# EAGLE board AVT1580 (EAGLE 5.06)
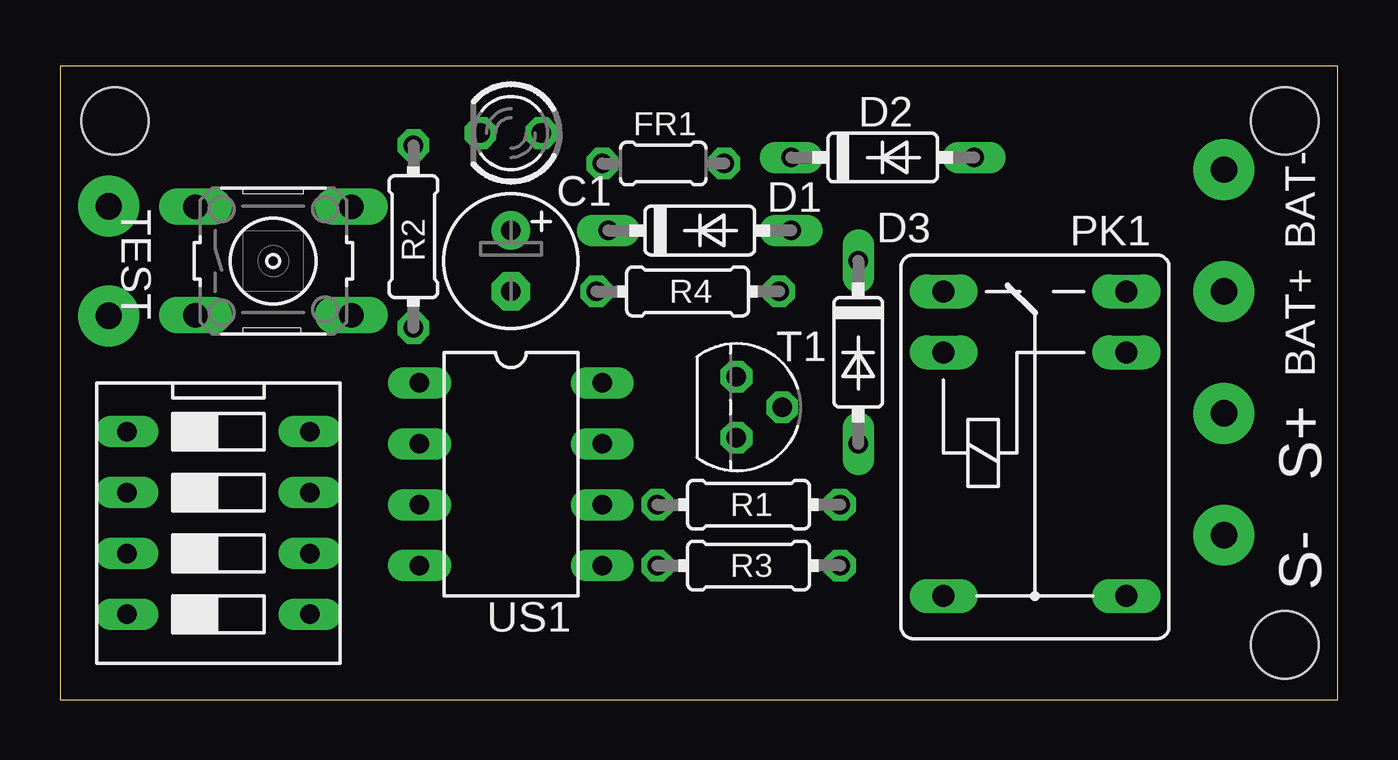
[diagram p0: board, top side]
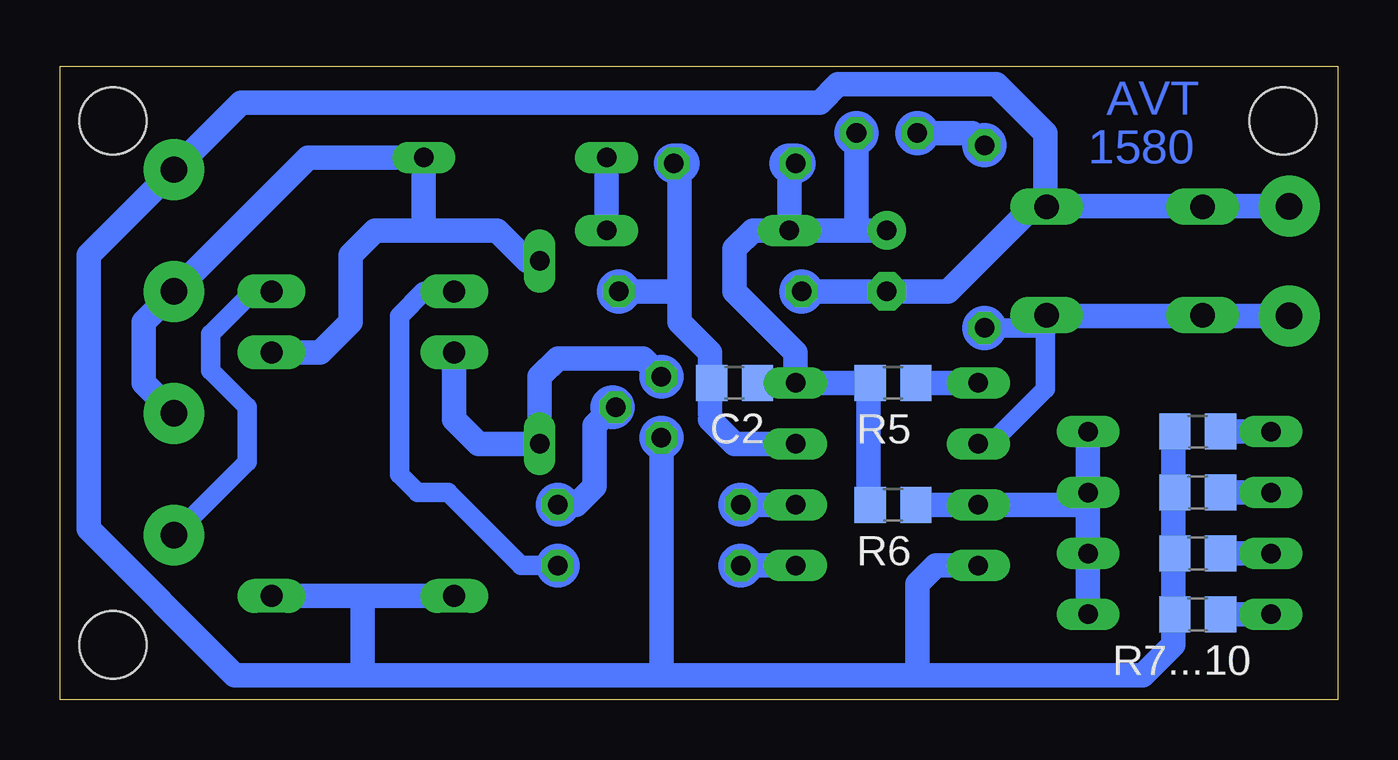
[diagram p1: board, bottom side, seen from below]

Size 53.26 x 26.41 mm. Coordinates in mm from the lower left corner, seen from the top.
Outline: 0,0 53.26,0 53.26,26.41 0,26.41 0,0
Copper layers (1*16): Top 0.035mm / dielectric 1.5mm / Bottom 0.035mm
Design rules "default": minimum track width 10mil, minimum drill 24mil, track to track 8mil, track to pad 8mil, pad to pad 8mil, via to via 8mil, smd to smd 8mil, copper to edge 40mil, drill to drill 8mil, minimum pad ring 10mil, minimum via ring 8mil, stop-mask expansion 4mil, vias tented up to drill 0mil, thermal gap 10mil
Holes 2.8 mm at 2.29,24.13 51.05,2.29 51.05,24.13

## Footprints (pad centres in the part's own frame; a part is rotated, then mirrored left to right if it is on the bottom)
E2,5-6 = drill 0.813 pad 1.6 round: + -1.27,0 | drill 0.813 pad 1.6 octagon: - 1.27,0
C0805 = smd 1.3 x 1.5: 1 -0.95,0; 2 0.95,0
DO35-7 = drill 0.813 long: A 3.81,0; C -3.81,0
LED3MM = drill 0.813 octagon: A -1.27,0; K 1.27,0
0204/5 = drill 0.813 octagon: 1 -2.54,0; 2 2.54,0
FRS1B = drill 0.914 long: 1 0,3.81; 2 0,-3.81; O -2.54,-3.81; P 10.16,3.81; P@ 10.16,-3.81; S -2.54,3.81
0204/7 = drill 0.813 octagon: 1 -3.81,0; 2 3.81,0
DS-04 = drill 0.813 long: 1 -3.81,-3.81; 2 -1.27,-3.81; 3 1.27,-3.81; 4 3.81,-3.81; 5 3.81,3.81; 6 1.27,3.81; 7 -1.27,3.81; 8 -3.81,3.81
TO92 = drill 0.813 octagon: 1 1.27,0; 2 0,1.905; 3 -1.27,0
B3F-10XX = drill 1.016 long: 1 -3.251,2.261; 2 3.251,2.261; 3 -3.251,-2.261; 4 3.251,-2.261
DIL08 = drill 0.813 long: 1 -3.81,-3.81; 2 -1.27,-3.81; 3 1.27,-3.81; 4 3.81,-3.81; 5 3.81,3.81; 6 1.27,3.81; 7 -1.27,3.81; 8 -3.81,3.81

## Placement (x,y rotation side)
C1  [E2,5-6]  18.8,18.29 270 top
C2  [C0805]  25.15,13.21 180 bottom
D1  [DO35-7]  26.67,19.56 0 top
D2  [DO35-7]  34.29,22.61 0 top
D3  [DO35-7]  33.27,14.48 270 top
E$3  [C0805]  5.84,8.64 0 bottom
E$4  [C0805]  5.84,6.1 0 bottom
E$5  [C0805]  5.84,3.56 0 bottom
E$9  [LED3MM]  18.8,23.62 180 top
FR1  [0204/5]  25.15,22.35 0 top
PK1  FRS1B  [FRS1B]  40.64,14.48 270 top
R1  [0204/7]  28.7,8.13 0 top
R2  [0204/7]  14.73,19.3 90 top
R3  [0204/7]  28.7,5.59 0 top
R4  [0204/7]  26.16,17.02 0 top
R5  [C0805]  18.54,13.21 0 bottom
R6  [C0805]  18.54,8.13 0 bottom
R7...10  [C0805]  5.84,11.18 0 bottom
S1  [DS-04]  6.6,7.37 270 top
T1  [TO92]  28.19,12.19 270 top
TEST  [B3F-10XX]  8.89,18.29 0 top
US1  [DIL08]  18.8,9.4 270 top

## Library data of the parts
C1 C2 E$3-E$5 FR1 R1-R6 R7...10 = rcl
D1-D3 = diode
E$9 = led
PK1 = relay
S1 = switch-dil
T1 = transistor-npn
TEST = switch-omron
US1 = atmel

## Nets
N$1: C1.- R4.1 US1.4
N$2: R2.1 US1.2
S$1: R1.1 US1.6
S$2: S1.5 S1.8
S$3: T1.1
S$5: D3.A PK1.2 T1.3
S$6: R1.2
S$8: E$9.K R2.2
S$9: D1.A D2.C
S$12: S1.1
S$13: FR1.2 R4.2
S$14: S1.2
S$15: S1.3
S$16: S1.4
S$18: US1.1
S$19: D2.A
S$20: R3.1 US1.5
S$22: PK1.O R3.2
S$25: PK1.P PK1.P@
S$26: D3.C PK1.1
S$29: PK1.S
VCC: C1.+ E$9.A FR1.1 US1.8

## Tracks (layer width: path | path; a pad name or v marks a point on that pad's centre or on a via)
N$1  (via drill 1.1 pad 2.54)
  Bottom 1.016: R4.1 C1.- 16.26,17.02 12.7,20.57 12.19,20.57 | 12.19,20.57 12.19,23.62 14.22,25.65 20.83,25.65 21.59,24.89 45.72,24.89 v48.51,22.1 52.07,18.54 52.07,7.11 45.97,1.02 40.64,1.02 | v2.03,20.57 12.19,20.57 | US1.4 16.76,5.59 17.53,4.83 17.53,1.02 40.64,1.02 | 40.64,4.06 40.64,1.02
N$2  (via drill 1.1 pad 2.54)
  Bottom 0.813: US1.2 14.48,10.67 12.19,12.95 12.19,15.49 | 12.19,15.49 12.19,16 12.45,16 | R2.1 12.19,15.49
  Bottom 1.016: v2.03,16 12.19,16
S$1
  Bottom 1.016: R1.1 US1.6
S$2
  Bottom 1.016: S1.5 S1.8
S$3
  Bottom 1.016: 28.19,1.27 T1.1
S$4
  Bottom 0.813: 24.38,13.21 22.61,13.21
  Bottom 1.016: 22.61,13.21 19.56,13.21 19.56,8.13
S$5
  Bottom 1.016: T1.3 28.96,14.22 32.51,14.22 33.27,13.46 D3.A 35.81,10.67 36.83,11.68 PK1.2
S$6
  Bottom 1.016: 30.23,12.19 30.99,11.43 30.99,8.89 31.75,8.13 R1.2
S$7
  Bottom 1.016: 22.61,10.67 25.15,10.67 26.16,11.68
S$8
  Bottom 1.016: E$9.K 15.24,23.62 R2.2
S$9
  Bottom 1.016: D1.A D2.C
S$10
  Bottom 1.016: 14.73,8.13 10.41,8.13 10.41,6.1
S$11
  Bottom 1.016: 17.53,8.13 14.99,8.13
S$12
  Bottom 1.016: S1.1 4.57,11.18
S$13
  Bottom 1.016: 27.43,17.02 R4.2 | 27.43,17.02 27.43,22.35 | 27.43,17.02 27.43,15.75 26.16,14.48 26.16,11.94
  Bottom 1.676: 27.43,22.35 FR1.2
S$14
  Bottom 1.016: S1.2 4.57,8.64
S$15
  Bottom 1.016: S1.3 4.57,6.1
S$16
  Bottom 1.016: S1.4 4.83,3.56
S$17
  Bottom 1.016: 6.86,11.18 6.86,2.29 8.13,1.02 17.78,1.02
S$18
  Bottom 1.016: US1.1 17.27,13.21
S$19  (via drill 1.1 pad 2.54)
  Bottom 1.016: v48.51,11.94 49.78,13.21 49.78,15.75 v48.51,17.02 42.93,22.61 D2.A 38.1,19.81
S$20
  Bottom 1.016: R3.1 US1.5
S$22
  Bottom 0.813: PK1.O 38.1,17.02 39.12,16 39.12,9.4 38.35,8.64 37.08,8.64 34.04,5.59 R3.2
S$25
  Bottom 1.016: PK1.P@ PK1.P
S$26
  Bottom 1.016: D3.C 33.78,18.29 35.05,19.56 40.13,19.56 41.15,18.54 41.15,15.75 42.42,14.48 PK1.1
S$29  (via drill 1.1 pad 2.54)
  Bottom 0.813: PK1.S 45.21,17.02 46.99,15.24 46.99,13.72 45.47,12.19 45.47,9.91 v48.51,6.86
VCC
  Bottom 1.016: C1.+ 20.07,19.56 | 20.07,19.56 22.86,19.56 | 22.86,19.56 23.11,19.56 24.38,19.56 25.15,18.8 25.15,17.02 22.61,14.48 US1.8 19.56,13.21 | 22.86,22.35 22.86,19.56 | E$9.A 20.07,19.56
  Bottom 1.676: FR1.1 22.86,22.35
(copper drawn outside any net)
  shapes: Bottom circle x13

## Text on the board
Bottom: AVT | 1580
tNames: BAT- | BAT+ | S+ | S-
